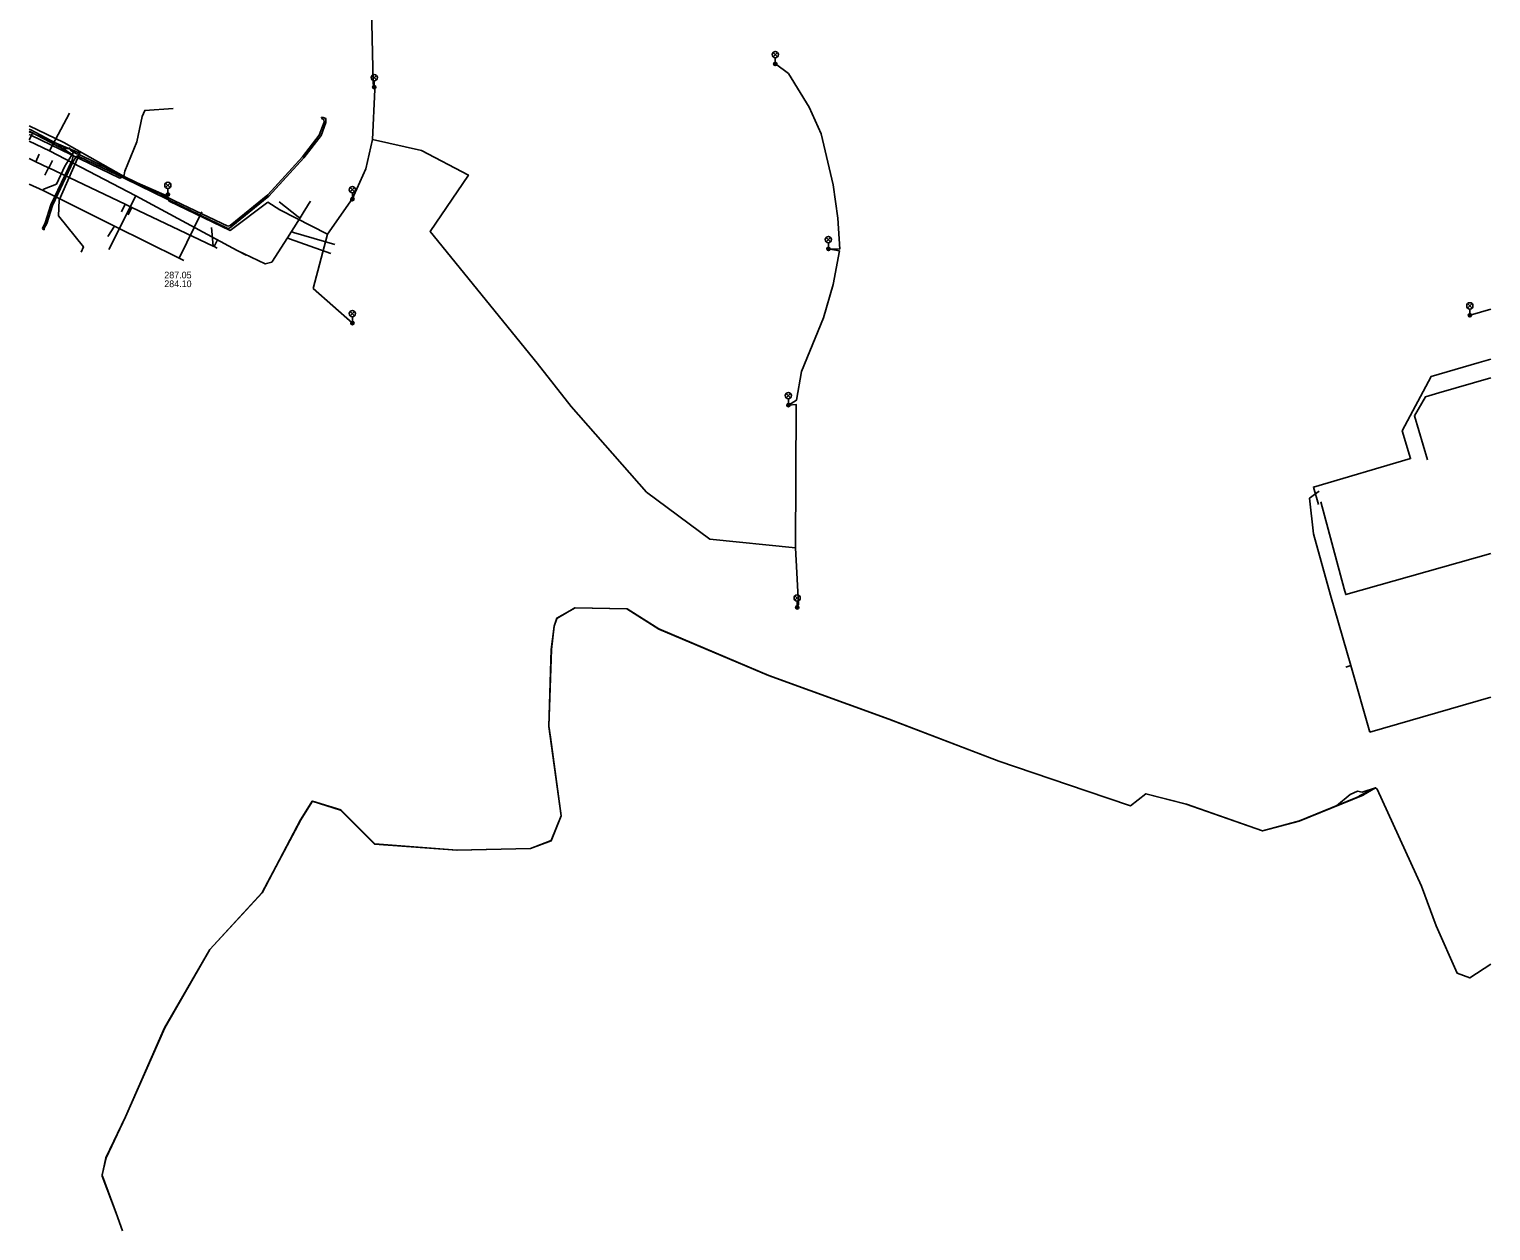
# Model space of a CAD drawing. Extents: x -599854 to -599675, y -1160809 to -1160543.
# Drawn here: x -599854.4 to -599679.2, y -1160809.2 to -1160665.1 of the extents above; entities that cross this region are included whole.
import ezdxf

# ---------------------------------------------------------------- set-up
doc = ezdxf.new("R2010")
doc.units = 0
for name, color, linetype in [('BVK-JEDNOTNA_popisy', 7, 'Continuous'), ('BVK-JEDNOTNA_trasa sítě', 7, 'Continuous'), ('BVK-VODOVOD_trasa sítě', 7, 'Continuous'), ('BVK-VODOVOD_trasa zrušené sítě', 7, 'Continuous'), ('CETIN_kabel podzemní', 7, 'Continuous'), ('DESTOVA_trasa neprovozované sítě', 7, 'Continuous'), ('DSP-DESTOVA-BVK_trasa podzemní sítě', 7, 'Continuous'), ('DSP-SDEL-MU_kabel', 7, 'Continuous'), ('DSP-TSB_kabel VO', 7, 'Continuous'), ('EON-NN_kabel', 7, 'Continuous'), ('EON-SDEL_kabel', 7, 'Continuous'), ('INNOGY-STL_trasa sítě', 7, 'Continuous'), ('JEDNOTNA_trasa neprovozované sítě', 7, 'Continuous'), ('QUANTCOM_kabel', 7, 'Continuous'), ('TSB_kabel VO', 7, 'Continuous'), ('TSB_lampy VO', 7, 'Continuous')]:
    doc.layers.add(name, color=color, linetype=linetype)

msp = doc.modelspace()

# ---------------------------------------------------------------- linework, layer by layer
at = {"layer": 'BVK-JEDNOTNA_popisy'}
msp.add_line((-599838.19, -1160695.135), (-599838.19, -1160695.135), dxfattribs=at)
at = {"layer": 'BVK-JEDNOTNA_trasa sítě'}
msp.add_lwpolyline([(-599831.84, -1160691.37), (-599832.211, -1160691.193), (-599832.338, -1160691.133), (-599842.073, -1160686.502), (-599842.876, -1160686.12), (-599852.033, -1160681.764), (-599852.06, -1160681.751), (-599853.595, -1160681.021), (-599854.3744, -1160680.6502)], dxfattribs=at)
at = {"layer": 'BVK-VODOVOD_trasa sítě'}
for p, q in [((-599851.942, -1160679.729), (-599849.562, -1160675.205)), ((-599841.599, -1160685.113), (-599844.82, -1160691.564)), ((-599821.031, -1160686.323), (-599820.9, -1160686.11)), ((-599820.9, -1160686.11), (-599820.68, -1160685.76))]:
    msp.add_line(p, q, dxfattribs=at)
for points in [[(-599854.3744, -1160678.5718), (-599851.942, -1160679.729), (-599841.599, -1160685.113), (-599829.45, -1160691.68)], [(-599829.45, -1160691.68), (-599826.08, -1160693.27), (-599825.32, -1160693.08), (-599823.43, -1160690.14), (-599822.95, -1160689.39), (-599821.91, -1160687.76), (-599821.55, -1160687.16), (-599821.031, -1160686.323)], [(-599821.91, -1160687.76), (-599822.13, -1160687.63), (-599824.43, -1160685.84)], [(-599823.43, -1160690.14), (-599823.18, -1160690.252), (-599818.23, -1160692.04)], [(-599822.95, -1160689.39), (-599822.699, -1160689.494), (-599817.76, -1160690.93)]]:
    msp.add_lwpolyline(points, dxfattribs=at)
at = {"layer": 'BVK-VODOVOD_trasa zrušené sítě'}
msp.add_line((-599829.45, -1160691.68), (-599828.385, -1160692.244), dxfattribs=at)
at = {"layer": 'CETIN_kabel podzemní'}
for points in [[(-599837.12, -1160674.65), (-599840.54, -1160674.87), (-599840.84, -1160675.61), (-599841.47, -1160678.65), (-599842.93, -1160682.16), (-599843.04, -1160682.81), (-599843.53, -1160682.99), (-599854.18, -1160677.84), (-599854.3744, -1160677.7419)], [(-599854.3744, -1160677.455), (-599848.33, -1160679.98), (-599850.79, -1160685.62), (-599850.86, -1160687.52), (-599847.88, -1160691.22), (-599848.17, -1160691.85)], [(-599745.7, -1160750), (-599751.33, -1160747.84), (-599765.76, -1160742.6), (-599778.91, -1160737.04), (-599782.73, -1160734.61), (-599788.95, -1160734.51), (-599791.13, -1160735.76), (-599791.45, -1160736.69), (-599791.8, -1160739.48), (-599792.09, -1160748.71), (-599791.91, -1160750)], [(-599843.1795, -1160809.1849), (-599843.94, -1160807.08), (-599845.6, -1160802.63), (-599845.63, -1160802.49), (-599845.17, -1160800.43), (-599842.82, -1160795.51), (-599838.13, -1160784.84), (-599832.72, -1160775.46), (-599826.45, -1160768.65), (-599821.84, -1160759.9), (-599820.43, -1160757.69), (-599817.05, -1160758.74), (-599812.97, -1160762.81), (-599803.1, -1160763.55), (-599794.29, -1160763.35), (-599791.82, -1160762.41), (-599790.61, -1160759.44), (-599791.91, -1160750)], [(-599697.697, -1160758.237), (-599702.16, -1160760.05), (-599706.57, -1160761.23), (-599715.69, -1160758.03), (-599720.56, -1160756.79), (-599722.38, -1160758.23), (-599727.7, -1160756.43), (-599738.17, -1160752.89), (-599745.7, -1160750)], [(-599696.07, -1160756.87), (-599697.697, -1160758.237)], [(-599695.2, -1160756.48), (-599696.07, -1160756.87)], [(-599679.2237, -1160777.2365), (-599681.75, -1160778.88), (-599683.24, -1160778.32), (-599685.76, -1160772.63), (-599687.54, -1160767.88), (-599692.826, -1160756.259), (-599693.02, -1160756.08), (-599694.63, -1160756.62), (-599695.2, -1160756.48)]]:
    msp.add_lwpolyline(points, dxfattribs=at)
at = {"layer": 'DESTOVA_trasa neprovozované sítě'}
msp.add_line((-599832.536, -1160688.89), (-599832.338, -1160691.133), dxfattribs=at)
at = {"layer": 'DSP-DESTOVA-BVK_trasa podzemní sítě'}
for points in [[(-599699.883, -1160722.13), (-599700.47, -1160720.02), (-599688.83, -1160716.61), (-599689.844, -1160713.277), (-599686.384, -1160706.782), (-599680.619, -1160705.105), (-599679.2237, -1160704.6991)], [(-599679.2237, -1160706.9339), (-599685.449, -1160708.745), (-599687.061, -1160709.205), (-599688.372, -1160711.5), (-599686.822, -1160716.755)], [(-599679.2237, -1160728.0044), (-599696.597, -1160732.91), (-599696.78, -1160732.23), (-599699.59, -1160721.81)]]:
    msp.add_lwpolyline(points, dxfattribs=at)
at = {"layer": 'DSP-SDEL-MU_kabel'}
msp.add_lwpolyline([(-599695.02, -1160757.09), (-599693.02, -1160756.08), (-599692.826, -1160756.259), (-599687.54, -1160767.88), (-599685.76, -1160772.63), (-599683.24, -1160778.32), (-599681.75, -1160778.88), (-599679.2237, -1160777.2365)], dxfattribs=at)
at = {"layer": 'DSP-TSB_kabel VO'}
for p, q in [((-599699.79, -1160720.52), (-599700.93, -1160721.37)), ((-599700.93, -1160721.37), (-599700.46, -1160725.62)), ((-599700.46, -1160725.62), (-599698.42, -1160732.98)), ((-599696.592, -1160741.602), (-599695.997, -1160741.431)), ((-599679.2237, -1160745.2139), (-599693.71, -1160749.406))]:
    msp.add_line(p, q, dxfattribs=at)
msp.add_lwpolyline([(-599698.42, -1160732.98), (-599695.997, -1160741.431), (-599693.71, -1160749.406)], dxfattribs=at)
at = {"layer": 'EON-NN_kabel'}
for points in [[(-599854.3744, -1160677.3587), (-599854.29, -1160677.397), (-599850.091, -1160679.615), (-599849.12, -1160680.22), (-599849.096, -1160680.322), (-599849.244, -1160680.828), (-599851.772, -1160686.194), (-599852.464, -1160688.361), (-599852.797, -1160688.978), (-599852.695, -1160689.158), (-599852.574, -1160689.159), (-599852.57, -1160688.984), (-599852.27, -1160688.411), (-599851.586, -1160686.268), (-599849.062, -1160680.912), (-599848.751, -1160680.42), (-599848.593, -1160680.326), (-599848.44, -1160680.38), (-599842.93, -1160683.05), (-599836.143, -1160686.335), (-599830.65, -1160688.98), (-599830.46, -1160689.03), (-599830.191, -1160688.844), (-599825.65, -1160685.134), (-599821.477, -1160680.561), (-599819.39, -1160677.89), (-599818.82, -1160676.33), (-599818.847, -1160675.827), (-599819.164, -1160675.731), (-599819.36, -1160675.72), (-599819.228, -1160675.921), (-599819.062, -1160675.97), (-599819.04, -1160676.28), (-599819.62, -1160677.83), (-599821.631, -1160680.433), (-599825.788, -1160684.988), (-599830.283, -1160688.66), (-599830.59, -1160688.73)], [(-599854.3744, -1160677.1389), (-599854.202, -1160677.217), (-599849.997, -1160679.439), (-599849.728, -1160679.467), (-599849.668, -1160679.439), (-599849.641, -1160679.373), (-599849.537, -1160679.382), (-599849.35, -1160679.71), (-599848.67, -1160680.06), (-599848.38, -1160680.16), (-599842.85, -1160682.86), (-599836.057, -1160686.155), (-599830.59, -1160688.73)]]:
    msp.add_lwpolyline(points, dxfattribs=at)
at = {"layer": 'EON-SDEL_kabel'}
for points in [[(-599843.2035, -1160809.1849), (-599843.96, -1160807.091), (-599845.62, -1160802.641), (-599845.65, -1160802.501), (-599845.19, -1160800.441), (-599842.84, -1160795.521), (-599838.15, -1160784.851), (-599832.74, -1160775.471), (-599826.47, -1160768.661), (-599821.86, -1160759.911), (-599820.45, -1160757.701), (-599817.07, -1160758.751), (-599812.99, -1160762.821), (-599803.12, -1160763.561), (-599794.31, -1160763.361), (-599791.84, -1160762.421), (-599790.63, -1160759.451), (-599792.11, -1160748.721), (-599791.82, -1160739.491), (-599791.47, -1160736.701), (-599791.15, -1160735.771), (-599788.97, -1160734.521), (-599782.75, -1160734.621), (-599778.93, -1160737.051), (-599765.78, -1160742.611), (-599751.35, -1160747.851)], [(-599751.35, -1160747.851), (-599738.19, -1160752.901), (-599727.72, -1160756.441), (-599722.4, -1160758.241), (-599720.58, -1160756.801), (-599715.71, -1160758.041), (-599706.59, -1160761.241), (-599702.18, -1160760.061), (-599694.517, -1160756.948), (-599694.497, -1160756.937), (-599694.477, -1160756.926), (-599693.02, -1160756.08), (-599692.826, -1160756.259), (-599687.54, -1160767.88), (-599685.76, -1160772.63), (-599683.24, -1160778.32), (-599681.75, -1160778.88), (-599679.2237, -1160777.2365)]]:
    msp.add_lwpolyline(points, dxfattribs=at)
at = {"layer": 'INNOGY-STL_trasa sítě'}
for points in [[(-599854.3744, -1160678.4163), (-599854.01, -1160677.74)], [(-599852.72, -1160684.49), (-599852.7, -1160684.37), (-599852.54, -1160684.26), (-599851.11, -1160683.72), (-599850.1, -1160681.55), (-599848.91, -1160679.64)], [(-599854.3744, -1160683.7112), (-599852.72, -1160684.49), (-599844.17, -1160688.74), (-599836.42, -1160692.57), (-599835.918, -1160692.817), (-599835.83, -1160692.86)], [(-599836.42, -1160692.57), (-599833.67, -1160687.05)], [(-599844.17, -1160688.74), (-599844.94, -1160690)]]:
    msp.add_lwpolyline(points, dxfattribs=at)
at = {"layer": 'JEDNOTNA_trasa neprovozované sítě'}
for p, q in [((-599853.166, -1160680.118), (-599853.595, -1160681.021)), ((-599851.603, -1160680.861), (-599852.033, -1160681.764)), ((-599852.49, -1160682.655), (-599852.06, -1160681.751)), ((-599843.306, -1160687.023), (-599842.876, -1160686.12)), ((-599842.502, -1160687.406), (-599842.073, -1160686.502)), ((-599831.782, -1160690.29), (-599832.211, -1160691.193))]:
    msp.add_line(p, q, dxfattribs=at)
at = {"layer": 'QUANTCOM_kabel'}
for points in [[(-599694.477, -1160756.926), (-599694.497, -1160756.937), (-599702.16, -1160760.05), (-599706.57, -1160761.23), (-599715.69, -1160758.03), (-599720.56, -1160756.79), (-599722.38, -1160758.23), (-599727.7, -1160756.43), (-599738.17, -1160752.89), (-599751.33, -1160747.84), (-599765.76, -1160742.6), (-599778.91, -1160737.04), (-599782.73, -1160734.61), (-599788.95, -1160734.51), (-599791.13, -1160735.76), (-599791.45, -1160736.69), (-599791.8, -1160739.48), (-599792.09, -1160748.71), (-599790.61, -1160759.44), (-599791.82, -1160762.41), (-599794.29, -1160763.35), (-599803.1, -1160763.55), (-599812.97, -1160762.81), (-599817.05, -1160758.74), (-599820.43, -1160757.69), (-599821.84, -1160759.9), (-599826.45, -1160768.65), (-599832.72, -1160775.46), (-599838.13, -1160784.84), (-599842.82, -1160795.51), (-599845.17, -1160800.43), (-599845.63, -1160802.49), (-599845.6, -1160802.63), (-599843.94, -1160807.08), (-599843.1795, -1160809.1849)], [(-599679.2237, -1160777.2365), (-599681.75, -1160778.88), (-599683.24, -1160778.32), (-599685.76, -1160772.63), (-599687.54, -1160767.88), (-599692.826, -1160756.259), (-599693.02, -1160756.08), (-599694.477, -1160756.926)]]:
    msp.add_lwpolyline(points, dxfattribs=at)
at = {"layer": 'TSB_kabel VO'}
for points in [[(-599813.42, -1160659.01), (-599813.171, -1160671.571), (-599813.17, -1160671.63), (-599813.03, -1160672.07), (-599812.97, -1160672.38), (-599813.25, -1160678.35), (-599814.04, -1160681.88), (-599815.47, -1160685.08), (-599815.65, -1160685.5), (-599815.93, -1160685.83), (-599818.62, -1160689.72), (-599820.34, -1160696.23), (-599815.64, -1160700.36), (-599820.34, -1160696.23), (-599818.62, -1160689.72), (-599824.33, -1160686.8), (-599825.8, -1160685.89)], [(-599825.8, -1160685.89), (-599824.33, -1160686.8), (-599818.62, -1160689.72), (-599815.93, -1160685.83), (-599815.47, -1160685.08), (-599814.04, -1160681.88), (-599813.25, -1160678.35), (-599807.37, -1160679.67), (-599801.75, -1160682.63), (-599806.31, -1160689.4), (-599793.52, -1160705.18), (-599789.41, -1160710.38), (-599780.42, -1160720.62), (-599772.81, -1160726.27), (-599762.56, -1160727.33), (-599762.18, -1160734.06), (-599762.35, -1160734.43), (-599762.18, -1160734.06), (-599762.56, -1160727.33), (-599762.466, -1160710.127), (-599763.39, -1160710.2), (-599762.43, -1160709.61), (-599761.81, -1160706.17), (-599759.17, -1160699.75), (-599758.03, -1160695.73), (-599757.29, -1160691.71), (-599758.62, -1160691.47), (-599757.242, -1160691.493), (-599757.47, -1160687.79), (-599758.05, -1160683.81), (-599759.46, -1160677.7), (-599760.9, -1160674.48), (-599763.37, -1160670.45), (-599764.96, -1160669.29)], [(-599854.3744, -1160676.738), (-599850.24, -1160678.73), (-599842.458, -1160683.11), (-599837.88, -1160685.12)], [(-599837.88, -1160685.12), (-599837.61, -1160685.74), (-599830.3, -1160689.26), (-599825.8, -1160685.89)], [(-599679.2237, -1160698.7003), (-599681.71, -1160699.42)]]:
    msp.add_lwpolyline(points, dxfattribs=at)
at = {"layer": 'TSB_lampy VO'}
for p, q in [((-599765.237, -1160668.443), (-599764.707, -1160667.913)), ((-599765.237, -1160667.913), (-599764.707, -1160668.443)), ((-599765.237, -1160668.443), (-599764.707, -1160667.913)), ((-599765.237, -1160667.913), (-599764.707, -1160668.443)), ((-599764.972, -1160668.553), (-599764.972, -1160669.303)), ((-599764.972, -1160668.553), (-599764.972, -1160669.303)), ((-599813.295, -1160671.21), (-599812.765, -1160670.68)), ((-599813.295, -1160670.68), (-599812.765, -1160671.21)), ((-599813.295, -1160671.21), (-599812.765, -1160670.68)), ((-599813.295, -1160670.68), (-599812.765, -1160671.21)), ((-599813.03, -1160671.32), (-599813.03, -1160672.07)), ((-599813.03, -1160671.32), (-599813.03, -1160672.07)), ((-599838.025, -1160684.11), (-599837.495, -1160683.58)), ((-599838.025, -1160683.58), (-599837.495, -1160684.11)), ((-599838.025, -1160684.11), (-599837.495, -1160683.58)), ((-599838.025, -1160683.58), (-599837.495, -1160684.11)), ((-599837.76, -1160684.22), (-599837.76, -1160684.97)), ((-599837.76, -1160684.22), (-599837.76, -1160684.97)), ((-599815.915, -1160684.64), (-599815.385, -1160684.11)), ((-599815.915, -1160684.11), (-599815.385, -1160684.64)), ((-599815.915, -1160684.64), (-599815.385, -1160684.11)), ((-599815.915, -1160684.11), (-599815.385, -1160684.64)), ((-599815.65, -1160684.75), (-599815.65, -1160685.5)), ((-599815.65, -1160684.75), (-599815.65, -1160685.5)), ((-599758.868, -1160690.621), (-599758.338, -1160690.091)), ((-599758.868, -1160690.091), (-599758.338, -1160690.621)), ((-599758.868, -1160690.621), (-599758.338, -1160690.091)), ((-599758.868, -1160690.091), (-599758.338, -1160690.621)), ((-599758.603, -1160690.731), (-599758.603, -1160691.481)), ((-599758.603, -1160690.731), (-599758.603, -1160691.481)), ((-599815.905, -1160699.5), (-599815.375, -1160698.97)), ((-599815.905, -1160698.97), (-599815.375, -1160699.5)), ((-599815.905, -1160699.5), (-599815.375, -1160698.97)), ((-599815.905, -1160698.97), (-599815.375, -1160699.5)), ((-599681.995, -1160698.57), (-599681.465, -1160698.04)), ((-599681.995, -1160698.04), (-599681.465, -1160698.57)), ((-599681.995, -1160698.57), (-599681.465, -1160698.04)), ((-599681.995, -1160698.04), (-599681.465, -1160698.57)), ((-599681.73, -1160698.68), (-599681.73, -1160699.43)), ((-599681.73, -1160698.68), (-599681.73, -1160699.43)), ((-599815.64, -1160699.61), (-599815.64, -1160700.36)), ((-599815.64, -1160699.61), (-599815.64, -1160700.36)), ((-599763.665, -1160709.333), (-599763.135, -1160708.803)), ((-599763.665, -1160708.803), (-599763.135, -1160709.333)), ((-599763.665, -1160709.333), (-599763.135, -1160708.803)), ((-599763.665, -1160708.803), (-599763.135, -1160709.333)), ((-599763.4, -1160709.443), (-599763.4, -1160710.193)), ((-599763.4, -1160709.443), (-599763.4, -1160710.193)), ((-599762.607, -1160733.597), (-599762.077, -1160733.067)), ((-599762.607, -1160733.067), (-599762.077, -1160733.597)), ((-599762.607, -1160733.597), (-599762.077, -1160733.067)), ((-599762.607, -1160733.067), (-599762.077, -1160733.597)), ((-599762.342, -1160733.707), (-599762.342, -1160734.457)), ((-599762.342, -1160733.707), (-599762.342, -1160734.457))]:
    msp.add_line(p, q, dxfattribs=at)
for centre, radius in [((-599764.972, -1160668.178), 0.375), ((-599764.972, -1160668.178), 0.375), ((-599764.972, -1160669.303), 0.2), ((-599764.972, -1160669.303), 0.2), ((-599764.972, -1160669.303), 0.1445), ((-599764.972, -1160669.303), 0.1445), ((-599764.972, -1160669.303), 0.0876), ((-599764.972, -1160669.303), 0.0876), ((-599813.03, -1160670.945), 0.375), ((-599813.03, -1160670.945), 0.375), ((-599813.03, -1160672.07), 0.2), ((-599813.03, -1160672.07), 0.2), ((-599813.03, -1160672.07), 0.1445), ((-599813.03, -1160672.07), 0.1445), ((-599813.03, -1160672.07), 0.0876), ((-599813.03, -1160672.07), 0.0876), ((-599837.76, -1160683.845), 0.375), ((-599837.76, -1160683.845), 0.375), ((-599837.76, -1160684.97), 0.2), ((-599837.76, -1160684.97), 0.2), ((-599837.76, -1160684.97), 0.1445), ((-599837.76, -1160684.97), 0.1445), ((-599837.76, -1160684.97), 0.0876), ((-599837.76, -1160684.97), 0.0876), ((-599815.65, -1160684.375), 0.375), ((-599815.65, -1160684.375), 0.375), ((-599815.65, -1160685.5), 0.2), ((-599815.65, -1160685.5), 0.2), ((-599815.65, -1160685.5), 0.1445), ((-599815.65, -1160685.5), 0.1445), ((-599815.65, -1160685.5), 0.0876), ((-599815.65, -1160685.5), 0.0876), ((-599758.603, -1160690.356), 0.375), ((-599758.603, -1160690.356), 0.375), ((-599758.603, -1160691.481), 0.2), ((-599758.603, -1160691.481), 0.2), ((-599758.603, -1160691.481), 0.1445), ((-599758.603, -1160691.481), 0.1445), ((-599758.603, -1160691.481), 0.0876), ((-599758.603, -1160691.481), 0.0876), ((-599815.64, -1160699.235), 0.375), ((-599815.64, -1160699.235), 0.375), ((-599681.73, -1160698.305), 0.375), ((-599681.73, -1160698.305), 0.375), ((-599815.64, -1160700.36), 0.2), ((-599815.64, -1160700.36), 0.2), ((-599815.64, -1160700.36), 0.1445), ((-599815.64, -1160700.36), 0.1445), ((-599815.64, -1160700.36), 0.0876), ((-599815.64, -1160700.36), 0.0876), ((-599681.73, -1160699.43), 0.2), ((-599681.73, -1160699.43), 0.2), ((-599681.73, -1160699.43), 0.1445), ((-599681.73, -1160699.43), 0.1445), ((-599681.73, -1160699.43), 0.0876), ((-599681.73, -1160699.43), 0.0876), ((-599763.4, -1160709.068), 0.375), ((-599763.4, -1160709.068), 0.375), ((-599763.4, -1160710.193), 0.2), ((-599763.4, -1160710.193), 0.2), ((-599763.4, -1160710.193), 0.1445), ((-599763.4, -1160710.193), 0.1445), ((-599763.4, -1160710.193), 0.0876), ((-599763.4, -1160710.193), 0.0876), ((-599762.342, -1160733.332), 0.375), ((-599762.342, -1160733.332), 0.375), ((-599762.342, -1160734.457), 0.2), ((-599762.342, -1160734.457), 0.2), ((-599762.342, -1160734.457), 0.1445), ((-599762.342, -1160734.457), 0.1445), ((-599762.342, -1160734.457), 0.0876), ((-599762.342, -1160734.457), 0.0876)]:
    msp.add_circle(centre, radius, dxfattribs=at)

# ---------------------------------------------------------------- texts
at = {"layer": 'BVK-JEDNOTNA_popisy'}
for s, p in [('287.05', (-599838.19, -1160695.01)), ('284.10', (-599838.19, -1160696.06))]:
    msp.add_text(s, height=0.8, dxfattribs=at).set_placement(p)

doc.saveas('drawing.dxf')
